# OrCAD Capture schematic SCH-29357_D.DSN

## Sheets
1 TITLE / TOC / REV: title: X-FRDMPT2001EVM; rev: D; company: NXP Semiconductors; note: SCH-29357 PDF: SPF-29357; note: 6501 William Cannon Drive West; note: Austin, TX 78735-8598
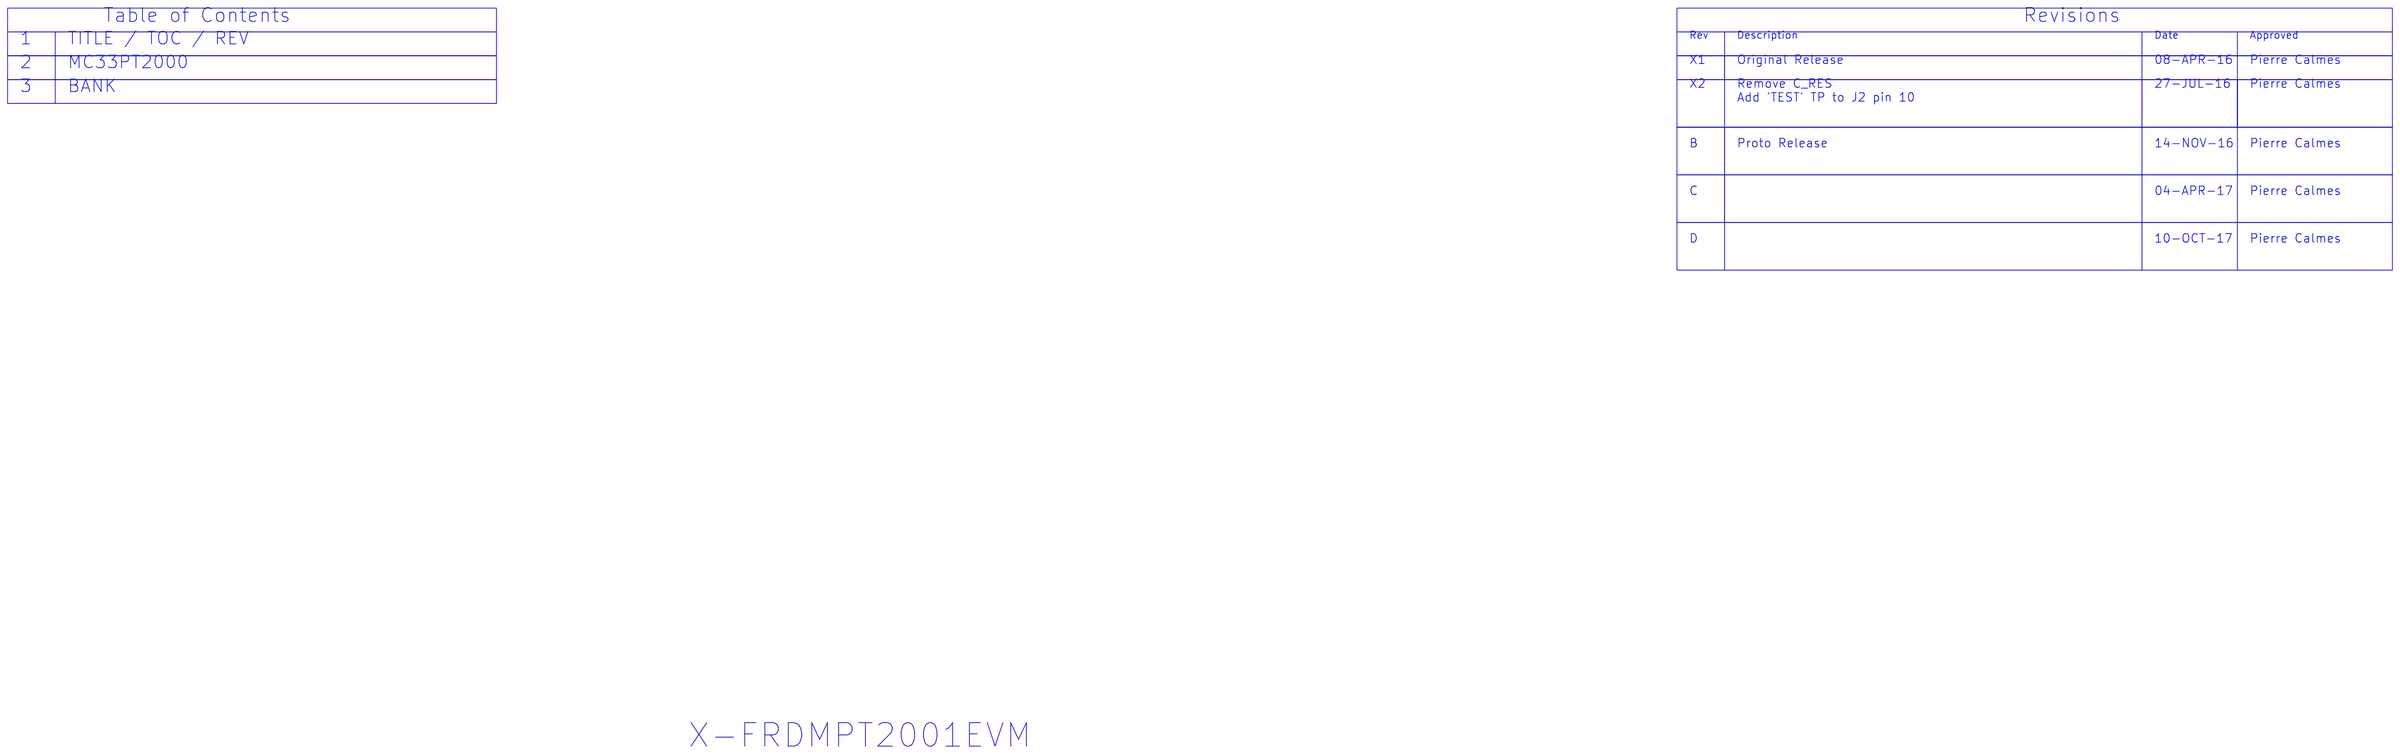
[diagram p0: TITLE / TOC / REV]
2 MC33PT2001: size Custom
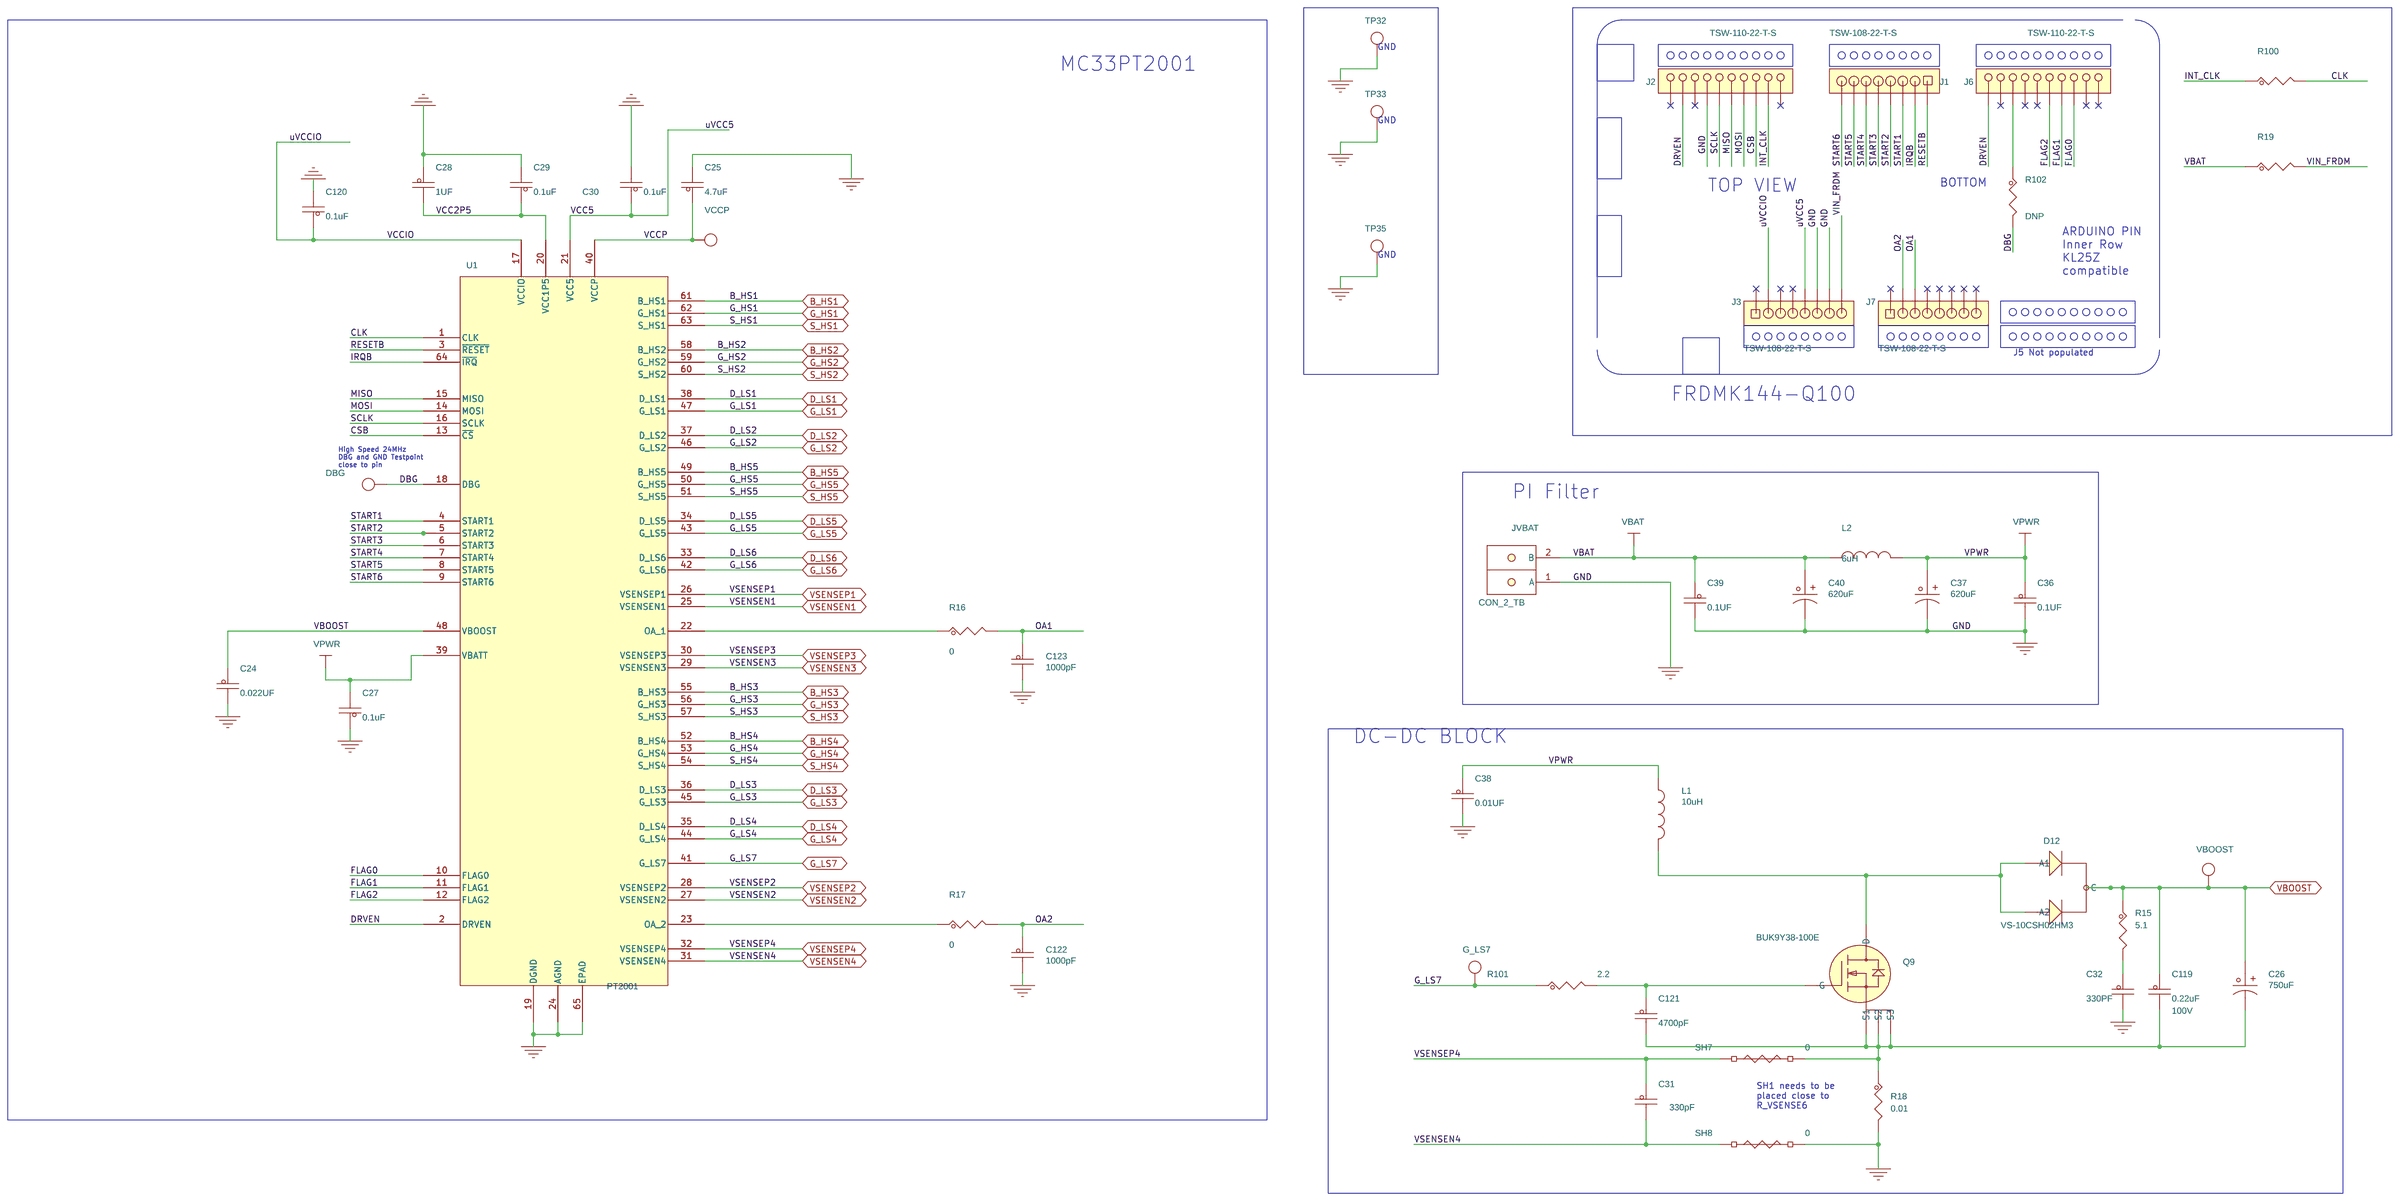
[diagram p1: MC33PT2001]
3 BANK: size Custom
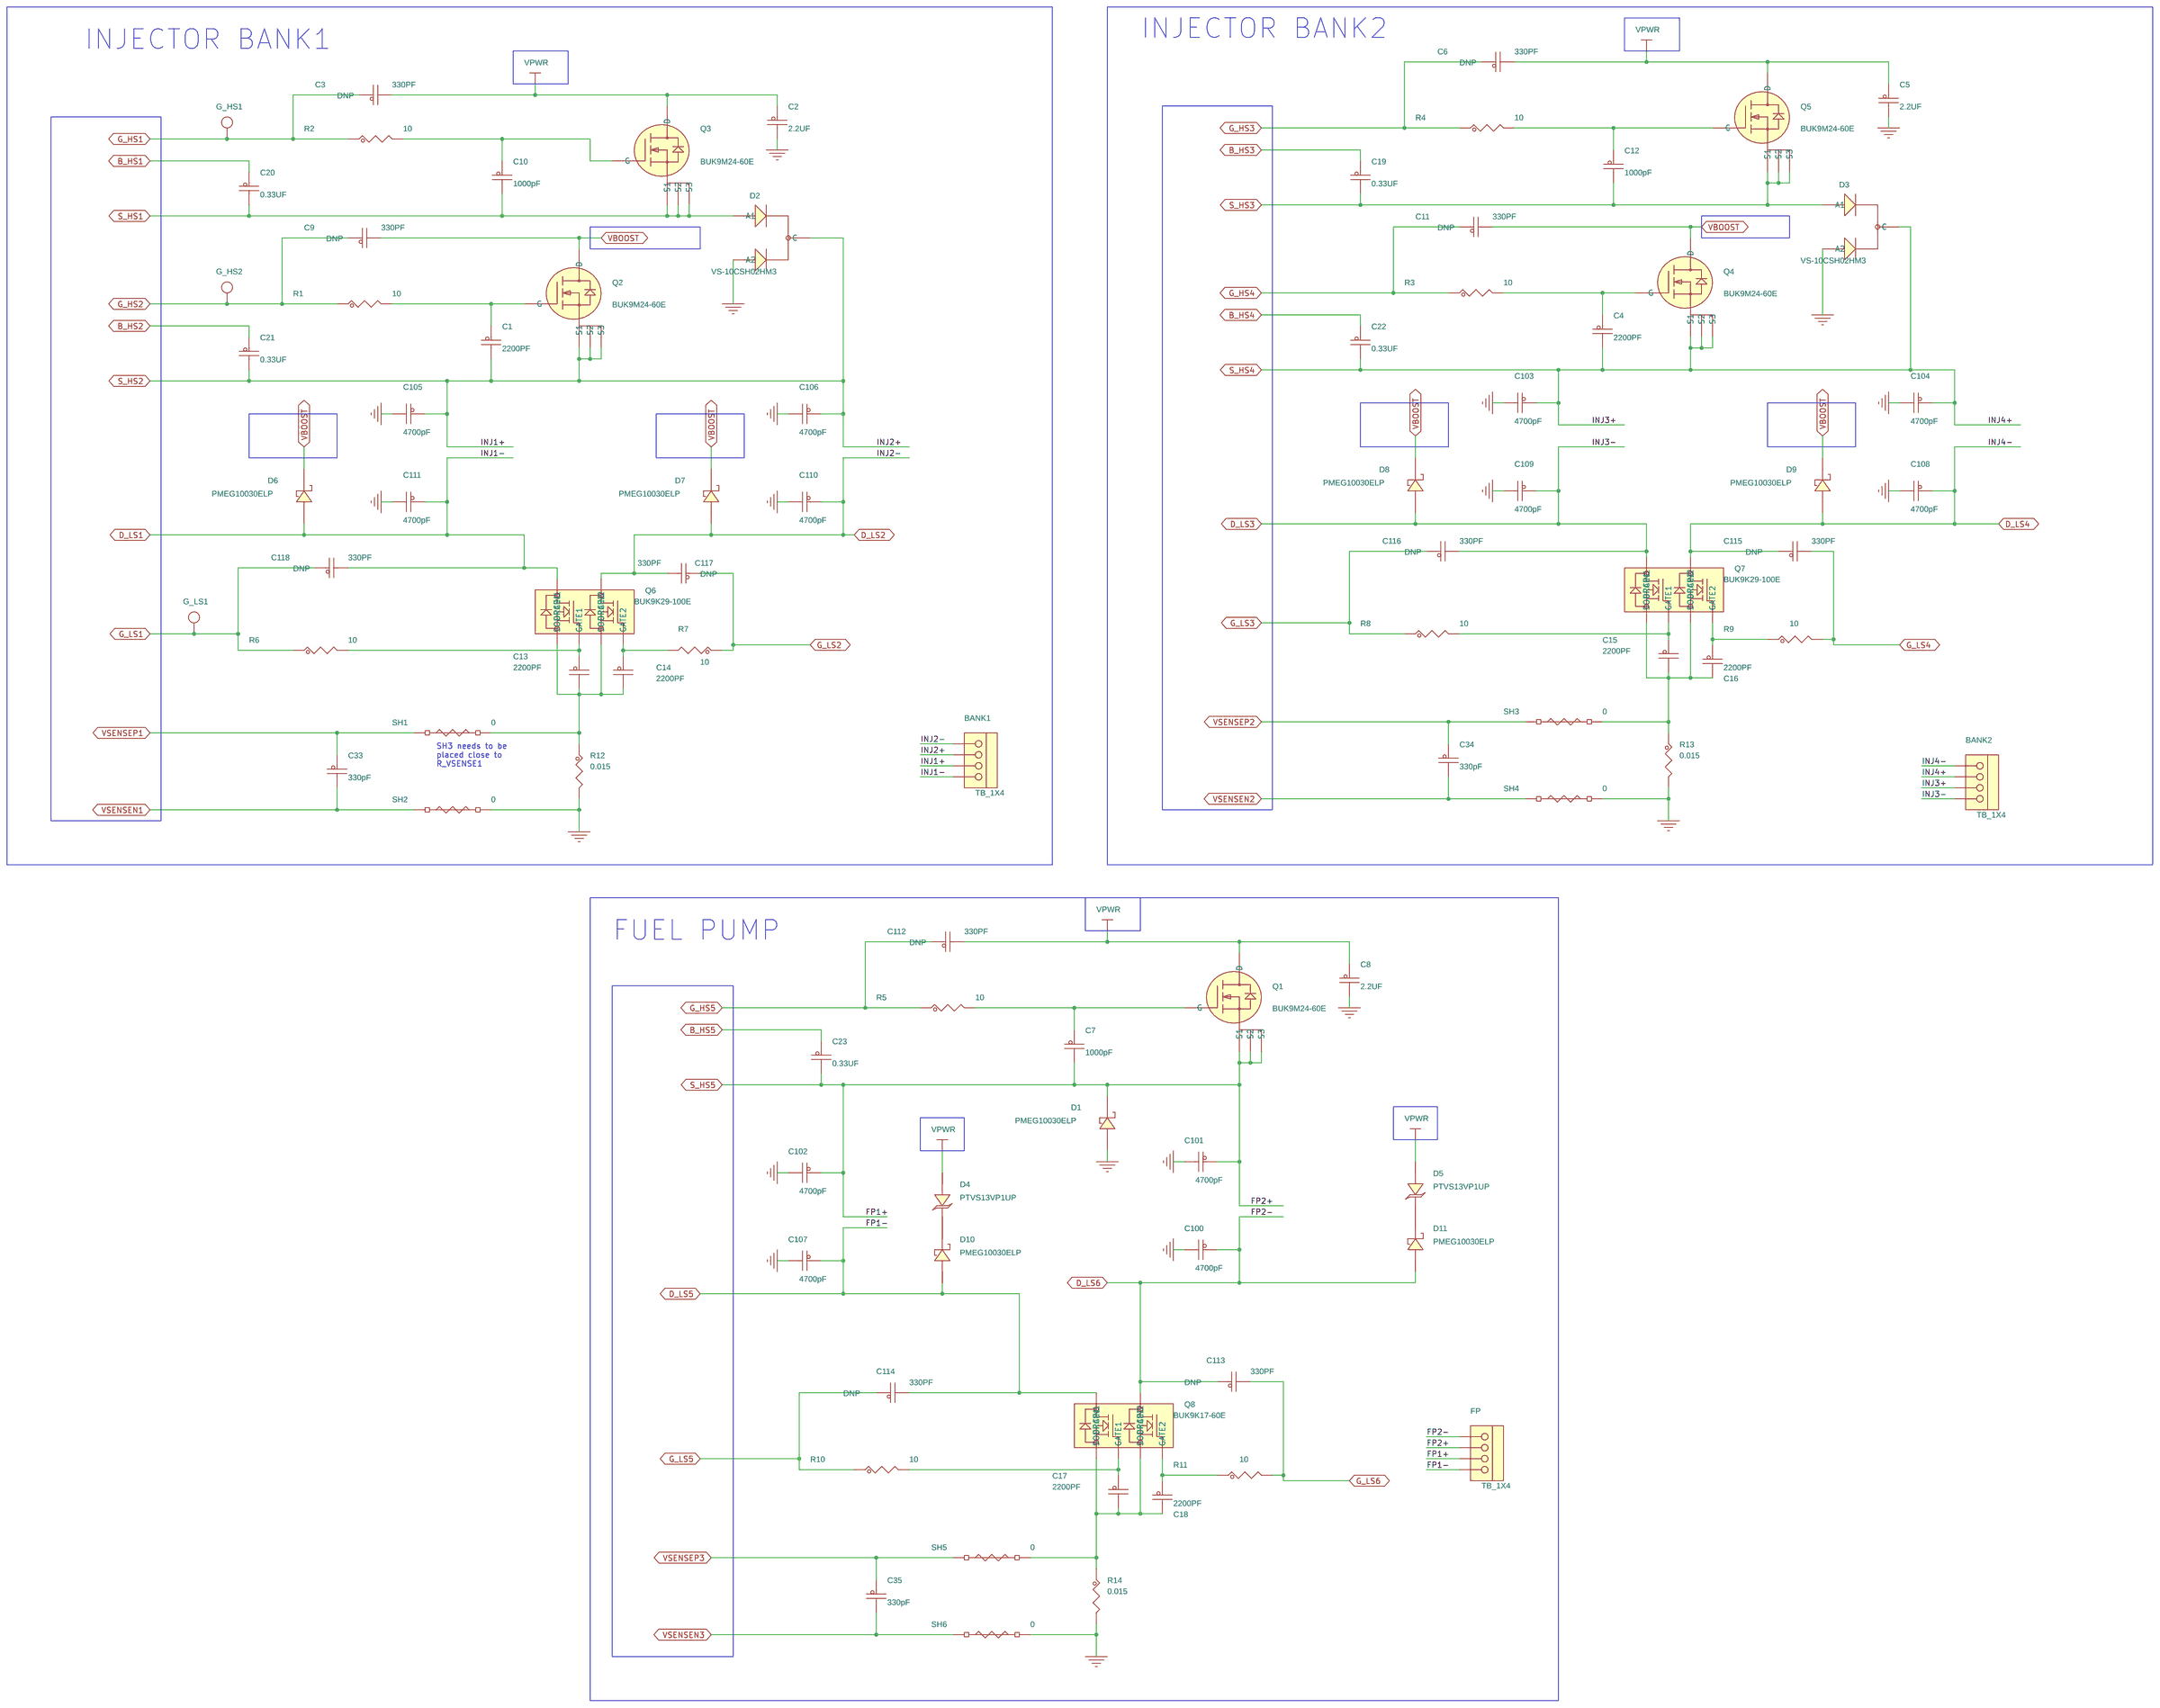
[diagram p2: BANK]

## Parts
sheet BANK
BANK1  TB_1X4  [con4_3p5_14p5x7mm]
BANK2  TB_1X4  [con4_3p5_14p5x7mm]
C1  2200PF  [CC0805_OV]
C2  2.2UF  [CC0805_OV]
C3  330PF  [CC0805_OV]
C4  2200PF  [CC0805_OV]
C5  2.2UF  [CC0805_OV]
C6  330PF  [CC0805_OV]
C7  1000pF  [CC0805_OV]
C8  2.2UF  [CC0805_OV]
C9  330PF  [CC0805_OV]
C10  1000pF  [CC0805_OV]
C11  330PF  [CC0805_OV]
C12  1000pF  [CC0805_OV]
C13  2200PF  [CC0805_OV]
C14  2200PF  [CC0805_OV]
C15  2200PF  [CC0805_OV]
C16  2200PF  [CC0805_OV]
C17  2200PF  [CC0805_OV]
C18  2200PF  [CC0805_OV]
C19  0.33UF  [CC0603_OV]
C20  0.33UF  [CC0603_OV]
C21  0.33UF  [CC0603_OV]
C22  0.33UF  [CC0603_OV]
C23  0.33UF  [CC0603_OV]
C33  330pF  [CC0603_OV]
C34  330pF  [CC0603_OV]
C35  330pF  [CC0603_OV]
C100  4700pF  [CC0805_OV]
C101  4700pF  [CC0805_OV]
C102  4700pF  [CC0805_OV]
C103  4700pF  [CC0805_OV]
C104  4700pF  [CC0805_OV]
C105  4700pF  [CC0805_OV]
C106  4700pF  [CC0805_OV]
C107  4700pF  [CC0805_OV]
C108  4700pF  [CC0805_OV]
C109  4700pF  [CC0805_OV]
C110  4700pF  [CC0805_OV]
C111  4700pF  [CC0805_OV]
C112  330PF  [CC0805_OV]
C113  330PF  [CC0805_OV]
C114  330PF  [CC0805_OV]
C115  330PF  [CC0805_OV]
C116  330PF  [CC0805_OV]
C117  330PF  [CC0805_OV]
C118  330PF  [CC0805_OV]
D1  PMEG10030ELP  [sod-128]
D2  VS-10CSH02HM3  [to_277a]
D3  VS-10CSH02HM3  [to_277a]
D4  PTVS13VP1UP  [sod-128]
D5  PTVS13VP1UP  [sod-128]
D6  PMEG10030ELP  [sod-128]
D7  PMEG10030ELP  [sod-128]
D8  PMEG10030ELP  [sod-128]
D9  PMEG10030ELP  [sod-128]
D10  PMEG10030ELP  [sod-128]
D11  PMEG10030ELP  [sod-128]
FP  TB_1X4  [con4_3p5_14p5x7mm]
G_HS1  TEST POINT ORANGE  [TEST_LOOP]
G_HS2  TEST POINT ORANGE  [TEST_LOOP]
G_LS1  TEST POINT ORANGE  [TEST_LOOP]
Q1  BUK9M24-60E  [LFPAK33_0P65_3P4X2P7]
Q2  BUK9M24-60E  [LFPAK33_0P65_3P4X2P7]
Q3  BUK9M24-60E  [LFPAK33_0P65_3P4X2P7]
Q4  BUK9M24-60E  [LFPAK33_0P65_3P4X2P7]
Q5  BUK9M24-60E  [LFPAK33_0P65_3P4X2P7]
Q6  BUK9K29-100E  [LFPAK56_1P27_4P7X5P3]
Q7  BUK9K29-100E  [LFPAK56_1P27_4P7X5P3]
Q8  BUK9K17-60E  [LFPAK56_1P27_4P7X5P3]
R1  10  [RC0805_OV]
R2  10  [RC0805_OV]
R3  10  [RC0805_OV]
R4  10  [RC0805_OV]
R5  10  [RC0805_OV]
R6  10  [RC0805_OV]
R7  10  [RC0805_OV]
R8  10  [RC0805_OV]
R9  10  [RC0805_OV]
R10  10  [RC0805_OV]
R11  10  [RC0805_OV]
R12  0.015  [rl3264]
R13  0.015  [rl3264]
R14  0.015  [rl3264]
SH1  0  [SH0603]
SH2  0  [SH0603]
SH3  0  [SH0603]
SH4  0  [SH0603]
SH5  0  [SH0603]
SH6  0  [SH0603]
sheet MC33PT2001
C24  0.022UF  [CC0805_OV]
C25  4.7uF  [CC0805_OV]
C26  750uF  [cap_pol_7p5_16p5]
C27  0.1uF  [CC0603_OV]
C28  1UF  [CC0603_OV]
C29  0.1uF  [CC0603_OV]
C30  0.1uF  [CC0603_OV]
C31  330pF  [CC0603_OV]
C32  330PF  [CC0805_OV]
C36  0.1UF  [CC1206_OV]
C37  620uF  [cap_13mm_rad]
C38  0.01UF  [CC0805_OV]
C39  0.1UF  [CC1206_OV]
C40  620uF  [cap_13mm_rad]
C119  0.22uF  [CC0805_OV]
C120  0.1uF  [CC0603_OV]
C121  4700pF  [CC0805_OV]
C122  1000pF  [CC0603_OV]
C123  1000pF  [CC0603_OV]
D12  VS-10CSH02HM3  [to_277a]
DBG  TEST POINT WHITE  [TEST_LOOP]
G_LS7  TEST POINT ORANGE  [TEST_LOOP]
J1  TSW-108-22-T-S  [JUMP1X8-6040]
J2  TSW-110-22-T-S  [hdr110]
J3  TSW-108-22-T-S  [JUMP1X8-6040]
J6  TSW-110-22-T-S  [hdr110]
J7  TSW-108-22-T-S  [JUMP1X8-6040]
JVBAT  CON_2_TB  [con2_tb_5mm]
L1  10uH  [ind_14x12p8]
L2  6uH  [ind2_18mm_th]
Q9  BUK9Y38-100E  [lfpak5_1p27_5x4]
R15  5.1  [RC0603_OV]
R16  0  [RC0603_OV]
R17  0  [RC0603_OV]
R18  0.01  [RC2512]
R19  0  [RC0603_OV]
R100  0  [RC0603_OV]
R101  2.2  [RC0805_OV]
R102  0  [RC0603_OV]
SH7  0  [SH0603]
SH8  0  [SH0603]
TP32  TEST POINT BLACK  [TEST_LOOP]
TP33  TEST POINT BLACK  [TEST_LOOP]
TP35  TEST POINT BLACK  [TEST_LOOP]
U1  PT2001  [LQFP64_EP175MIL]
VBOOST  TEST POINT RED  [TEST_LOOP]
VCCP  TEST POINT RED  [TEST_LOOP]

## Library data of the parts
BANK1 BANK2 FP = CON_HDR_1X4: CON 1X4 TB TH 3.5MM SP 335H -- 138L; AGILE_PN: 210-80422; CAD_APPROVED: Yes; HARD_LOCATION: YES; HEIGHT: 8.5MM; MFG_NAME01: Phoenix Contact; MFG_PN01: 1751264; ROHS: Yes
C1 C4 C13-C18 = CAP_NP: CAP CER 2200PF 25V 20% X7R 0805; AGILE_PN: 150-75211; CAD_APPROVED: YES; FPLIST: CC0805_OV,CC0805,0805_CC; HARD_LOCATION: YES; HEIGHT: 1.4MM; MFG_NAME01: KEMET; MFG_PN01: C0805C222M3RAC; ROHS: Yes; Tolerance: 20%; VOLTAGE: 25V
C2 C5 C8 = CAP_NP: CAP CER 2.2uF 25V 10% X7R 0805; AGILE_PN: 150-75638; CAD_APPROVED: Yes; FPLIST: CC0805_OV,CC0805,0805_CC; HARD_LOCATION: YES; HEIGHT: 1.45MM; MFG_NAME01: AVX; MFG_PN01: 08053C225KAT2A; ROHS: Yes; Tolerance: 10%; VOLTAGE: 25V
C3 C6 C9 C11 C112-C118 = CAP_NP: CAP CER 330PF 100V 5% C0G 0805; AGILE_PN: 150-77353; ASSY_OPT: DNP; CAD_APPROVED: Yes; FPLIST: CC0805_OV,CC0805,0805_CC; HARD_LOCATION: YES; HEIGHT: 0.94MM; MFG_NAME01: AVX; MFG_PN01: 08051A331JAT2A; ROHS: Yes; Tolerance: 5%; VOLTAGE: 100V
C7 C10 C12 = CAP_NP: CAP CER 1000PF 50V 10% X7R 0805; AGILE_PN: 150-75208; CAD_APPROVED: Yes; FPLIST: CC0805_OV,CC0805,0805_CC; HARD_LOCATION: YES; HEIGHT: 0.94MM; MFG_NAME01: AVX; MFG_PN01: 08055C102KAT2A; ROHS: Yes; Tolerance: 10%; VOLTAGE: 50V
C19-C23 = CAP_NP: CAP CER 0.33UF 50V 10% X7R 0603; AGILE_PN: 150-79257; CAD_APPROVED: Yes; FPLIST: CC0603_OV,CC0603,0603_CC; HARD_LOCATION: YES; HEIGHT: 0.9MM; MFG_NAME01: TDK; MFG_PN01: C1608X7R1H334K080AC; ROHS: Yes; Tolerance: 10%; VOLTAGE: 50V
C31 C33-C35 = CAP_NP: CAP CER 330PF 25V 1% C0G 0603; AGILE_PN: 150-77872; CAD_APPROVED: Yes; FPLIST: CC0603_OV,CC0603,0603_CC; HARD_LOCATION: YES; HEIGHT: 0.86MM; MFG_NAME01: AVX; MFG_PN01: 06033A331FAT2A; ROHS: Yes; Tolerance: 1%; VOLTAGE: 25V
C100-C111 C121 = CAP_NP: CAP CER 4700pF 100V 5% C0G 0805; AGILE_PN: 150-78729; CAD_APPROVED: Yes; FPLIST: CC0805_OV,CC0805,0805_CC; HARD_LOCATION: YES; HEIGHT: 0.88MM; MFG_NAME01: KEMET; MFG_PN01: C0805C472J1GACTU; ROHS: Yes; Tolerance: 5%; VOLTAGE: 100V
D1 D6-D11 = DIODE_SCHTKY: DIODE SCH 100V 3A AEC-Q101 SOD128; AGILE_PN: 480-78979; CAD_APPROVED: Yes; HARD_LOCATION: YES; HEIGHT: 1.1MM; MFG_NAME01: NXP SEMICONDUCTORS; ROHS: Yes
D2 D3 D12 = DUALDIODE_CC_SOT23: DIODE RECT 2 x 5A AEC-Q101 TO-277A; AGILE_PN: 480-79720; CAD_APPROVED: Yes; HARD_LOCATION: YES; HEIGHT: 1.2MM; MFG_NAME01: VISHAY INTERTECHNOLOGY; ROHS: Yes; Temp_Range: -65C to +175C
D4 D5 = DIODE_TVS: DIODE TVS UNIDIR 100A 600W 13V AEC-Q101 SOD128; AGILE_PN: 480-79663; CAD_APPROVED: Yes; HARD_LOCATION: YES; HEIGHT: 1.1MM; MFG_NAME01: NXP SEMICONDUCTORS; MFG_PN01: PTVS13VP1UP,115; ROHS: Yes
G_HS1 G_HS2 G_LS1 G_LS7 = TestLoop: TEST POINT ORANGE 40 MIL DRILL 180 MIL TH; AGILE_PN: 210-76025; CAD_APPROVED: Yes; HARD_LOCATION: YES; HEIGHT: 4.8 mm; MFG_NAME01: Keystone Electronics; MFG_PN01: 5003; ROHS: Yes
Q1-Q5 = NMOS_5P: TRAN NMOS PWR  24mOHM 34A 60V LFPAK33; AGILE_PN: 480-79524; CAD_APPROVED: Yes; HARD_LOCATION: YES; HEIGHT: 1 MM; MFG_NAME01: NXP SEMICONDUCTORS; MFG_PN01: BUK9M24-60EX; ROHS: Yes
Q6 Q7 = NMOS_DUAL_8P: TRAN NMOS PWR SW DUAL 29mOHM 30A 100V AEC-Q101 LFPAK56D; AGILE_PN: 480-79204; CAD_APPROVED: Yes; HARD_LOCATION: YES; HEIGHT: 1.15 MM; MFG_NAME01: NXP SEMICONDUCTORS; MFG_PN01: BUK9K29-100E,115; ROHS: Yes
Q8 = NMOS_DUAL_8P: TRAN NMOS PWR SW DUAL 17mOHM 26A 60V AEC-Q101 LFPAK56D; AGILE_PN: 480-79200; CAD_APPROVED: Yes; HARD_LOCATION: YES; HEIGHT: 1.15 MM; MFG_NAME01: NXP SEMICONDUCTORS; MFG_PN01: BUK9K17-60EX; ROHS: Yes
R1-R11 = RES: RES MF 10.0 OHM 1/8W 1% 0805; AGILE_PN: 470-75903; CAD_APPROVED: Yes; FPLIST: RC0805_OV,RC0805,0805_CC; HARD_LOCATION: YES; HEIGHT: 0.70 MM; MFG_NAME01: BOURNS; MFG_PN01: CR0805-FX-10R0ELF; ROHS: Yes; Tolerance: 1%
R12-R14 = RES: RES MF 0.015 OHM 2W 1% 2512; AGILE_PN: 470-80377; CAD_APPROVED: Yes; HARD_LOCATION: YES; HEIGHT: 0.62MM; MFG_NAME01: OHMITE MANUFACTURING; MFG_PN01: MCS3264R015FER; ROHS: Yes; Tolerance: 1%
SH1-SH8 = RES_SHORT-2: ZERO OHM CUT TRACE 0603 PADS; NO PART TO ORDER; AGILE_PN: 470-80018; CAD_APPROVED: Yes; FPLIST: SH0603,SH0603_CC,SH0603-X2_PIN1TO2,SH0603-X2_PIN2TO3; HARD_LOCATION: YES; HEIGHT: 0.1MM; MFG_NAME01: LAYOUT ELEMENT ONLY; MFG_PN01: LAYOUT ELEMENT ONLY; ROHS: Yes
C24 = CAP_NP: CAP CER 0.022UF 50V 10% X7R 0805; AGILE_PN: 150-30206; CAD_APPROVED: Yes; FPLIST: CC0805_OV,CC0805,0805_CC; HARD_LOCATION: YES; HEIGHT: 1.35MM; MFG_NAME01: KEMET; MFG_PN01: C0805C223K5RACTU; ROHS: Yes; Tolerance: 10%; VOLTAGE: 50V
C25 = CAP_NP: CAP CER 4.7uF 50V 20% X5R 0805; AGILE_PN: 150-78922; CAD_APPROVED: Yes; FPLIST: CC0805_OV,CC0805,0805_CC; HARD_LOCATION: YES; HEIGHT: 1.45MM; MFG_NAME01: TDK; MFG_PN01: C2012X5R1H475M; ROHS: Yes; Tolerance: 20%; VOLTAGE: 50V
C26 = CAP_POL: CAP ALEL 750uF 80V 20% TH RADIAL; AGILE_PN: 150-79865; CAD_APPROVED: Yes; HARD_LOCATION: YES; HEIGHT: 31.5MM; MFG_NAME01: UNITED CHEMI-CON INC; MFG_PN01: EGPD800ELL751ML30H; ROHS: Yes; Temp_Range: -40°C - 135°C; Tolerance: 20%; VOLTAGE: 80V
C27 C29 C30 C120 = CAP_NP: CAP CER 0.1uF 50V 10% X7R AEC-Q200 0603; AGILE_PN: 150-79042; CAD_APPROVED: Yes; FPLIST: CC0603_OV,CC0603,0603_CC; HARD_LOCATION: YES; HEIGHT: 0.9 MM; MFG_NAME01: MURATA; MFG_PN01: GCM188R71H104KA57D; ROHS: Yes; Tolerance: 10%; VOLTAGE: 50V
C28 = CAP_NP: CAP CER 1uF 25V 10% X7R AEC-Q200 0603; AGILE_PN: 150-79081; CAD_APPROVED: Yes; FPLIST: CC0603_OV,CC0603,0603_CC; HARD_LOCATION: YES; HEIGHT: 0.9MM; MFG_NAME01: TDK; MFG_PN01: CGA3E1X7R1E105K080AC; ROHS: Yes; Tolerance: 10%; VOLTAGE: 25V
C32 = CAP_NP: CAP CER 330PF 100V 5% C0G 0805; AGILE_PN: 150-77353; CAD_APPROVED: Yes; FPLIST: CC0805_OV,CC0805,0805_CC; HARD_LOCATION: YES; HEIGHT: 0.94MM; MFG_NAME01: AVX; MFG_PN01: 08051A331JAT2A; ROHS: Yes; Tolerance: 5%; VOLTAGE: 100V
C36 C39 = CAP_NP: CAP CER 0.1UF 200V 10% X7R 1206; AGILE_PN: 150-77157; CAD_APPROVED: Yes; FPLIST: CC1206_OV,CC1206,1206_CC; HARD_LOCATION: YES; HEIGHT: 1.8MM; MFG_NAME01: KEMET; MFG_PN01: C1206C104K2RACTU; ROHS: Yes; Tolerance: 10%; VOLTAGE: 200V
C37 C40 = CAP_POL: CAP ALEL 620uF 50V 20% -- TH RADIAL; AGILE_PN: 150-79766; CAD_APPROVED: Yes; HARD_LOCATION: YES; HEIGHT: 21.5MM; MFG_NAME01: UNITED CHEMI-CON INC; MFG_PN01: EGPD500ELL621MK20H; ROHS: Yes; Tolerance: 20%; VOLTAGE: 50V
C38 = CAP_NP: CAP CER 0.01UF 100V 10% X7R 0805; AGILE_PN: 150-30231; CAD_APPROVED: Yes; FPLIST: CC0805_OV,CC0805,0805_CC; HARD_LOCATION: YES; HEIGHT: 1.35MM; MFG_NAME01: MURATA; MFG_PN01: GRM21BR72A103KA01L; ROHS: Yes; Tolerance: 10%; VOLTAGE: 100V
C119 = CAP_NP: CAP CER 0.22UF 100V 20% X7S 0805; AGILE_PN: 150-79088; CAD_APPROVED: Yes; FPLIST: CC0805_OV,CC0805,0805_CC; HARD_LOCATION: YES; HEIGHT: 0.85MM; MFG_NAME01: TDK; MFG_PN01: C2012X7S2A224M/SOFT; ROHS: Yes; Tolerance: 20%; VOLTAGE: 100V
C122 C123 = CAP_NP: CAP CER 1000pF 50V 1% C0G 0603; AGILE_PN: 150-79073; CAD_APPROVED: Yes; FPLIST: CC0603_OV,CC0603,0603_CC; HARD_LOCATION: YES; HEIGHT: 0.9MM; MFG_NAME01: TDK; MFG_PN01: C1608C0G1H102F080AA; ROHS: Yes; Tolerance: 1%; VOLTAGE: 50V
DBG = TestLoop: TEST POINT WHITE 40 MIL DRILL 180 MIL TH 109L; AGILE_PN: 210-75685; CAD_APPROVED: Yes; HARD_LOCATION: YES; HEIGHT: 4.8 MM; MFG_NAME01: KEYSTONE ELECTRONICS; MFG_PN01: 5002; ROHS: Yes
J1 J3 J7 = HDR-1X8: HDR 1X8 TH 100MIL SP 338H SN 300L; AGILE_PN: 210-81229; CAD_APPROVED: Yes; HARD_LOCATION: YES; HEIGHT: 8.59MM; MFG_NAME01: SAMTEC; ROHS: Yes; Temp_Range: 55C to +105C
J2 J6 = CONN_HDR_10X1: HDR 1X10 TH 100MIL SP 338H SN 300L; AGILE_PN: 210-81230; CAD_APPROVED: Yes; HARD_LOCATION: YES; HEIGHT: 8.59MM; MFG_NAME01: SAMTEC; ROHS: Yes; Temp_Range: 55C to +105C
JVBAT = TB2: CON 1X2 TB TH 5MM SP 394H SN; AGILE_PN: 210-77613; CAD_APPROVED: Yes; HARD_LOCATION: YES; HEIGHT: 10MM; MFG_NAME01: CAMDEN ELECTRONICS LTD; MFG_PN01: CTB5000/2; ROHS: Yes
L1 = IND: IND PWR 10uH@100KHZ 16A 20% AEC-Q200 SMT; AGILE_PN: 180-78393; CAD_APPROVED: Yes; HARD_LOCATION: YES; HEIGHT: 5MM; MFG_NAME01: Bourns; MFG_PN01: SRP1245A-100M; PART_TYPE: INDUCTOR\POWER; ROHS: Yes; TOL: 20%; Tolerance: 20%
L2 = INDUCTOR: IND ROD CHK 6uH@10KHZ 10A 25% TH; AGILE_PN: 180-78068; CAD_APPROVED: Yes; HARD_LOCATION: YES; HEIGHT: 8.6MM; MFG_NAME01: WURTH ELEKTRONIK EISOS GMBH & CO. KG; MFG_PN01: 744710610; PART_TYPE: INDUCTOR\POWER; ROHS: Yes
Q9 = NMOS_5P: TRAN NMOS PWR 30A 100V AEC-Q101 LFPAK56; AGILE_PN: 480-78977; CAD_APPROVED: Yes; HARD_LOCATION: YES; HEIGHT: 1.2MM; MFG_NAME01: NXP SEMICONDUCTORS; MFG_PN01: BUK9Y38-100E,115; ROHS: Yes
R15 = RES: RES MF 5.1 OHM 1/10W 5% 0603; AGILE_PN: 470-30450; CAD_APPROVED: Yes; FPLIST: RC0603_OV,RC0603,0603_CC; HARD_LOCATION: YES; HEIGHT: 0.55 MM; MFG_NAME01: KOA SPEER; MFG_PN01: RK73B1JTTD5R1J; ROHS: Yes; Tolerance: 5%
R16 R17 = RES: RES MF ZERO OHM 1/10W -- 0603; AGILE_PN: 470-80866; CAD_APPROVED: Yes; FPLIST: RC0603_OV,RC0603,R603-X2,0603_CC; HARD_LOCATION: YES; HEIGHT: 0.6MM; MFG_NAME01: BOURNS; MFG_PN01: CR0603J/000ELF; ROHS: Yes
R18 = RES: RES MF 0.01 OHM 1.0W 1% 2512; AGILE_PN: 470-75760; CAD_APPROVED: Yes; HARD_LOCATION: YES; HEIGHT: 1.016 MM; MFG_NAME01: VISHAY INTERTECHNOLOGY; MFG_PN01: WSL2512R0100FEA; ROHS: Yes; Tolerance: 1%
R19 R100 = RES: RES MF ZERO OHM 1/10W -- AEC-Q200 0603; AGILE_PN: 470-75407; CAD_APPROVED: Yes; FPLIST: RC0603_OV,RC0603,R603-X2,0603_CC; HARD_LOCATION: YES; HEIGHT: 0.6MM; MFG_NAME01: KOA SPEER; MFG_PN01: RK73Z1JTTD; ROHS: Yes; Tolerance: 1%
R101 = RES: RES MF 2.20 OHM 1/8W 1% 0805; AGILE_PN: 470-76034; CAD_APPROVED: Yes; FPLIST: RC0805_OV,RC0805,0805_CC; HARD_LOCATION: YES; MFG_NAME01: BOURNS; MFG_PN01: CRL0805-FW-2R20ELF; ROHS: Yes; Tolerance: 1%
R102 = RES: RES MF ZERO OHM 1/10W -- AEC-Q200 0603; AGILE_PN: 470-75407; ASSY_OPT: DNP; CAD_APPROVED: Yes; FPLIST: RC0603_OV,RC0603,R603-X2,0603_CC; HARD_LOCATION: YES; HEIGHT: 0.6MM; MFG_NAME01: KOA SPEER; MFG_PN01: RK73Z1JTTD; ROHS: Yes; Tolerance: 1%
TP32 TP33 TP35 = TestLoop: TEST POINT BLACK 40 MIL DRILL 180 MIL TH 109L; AGILE_PN: 210-75683; CAD_APPROVED: Yes; HARD_LOCATION: YES; HEIGHT: 4.8mm; MFG_NAME01: KEYSTONE ELECTRONICS; MFG_PN01: 5001; ROHS: Yes
U1 = PT2001_LQFP64_EP: IC CTLER AUTOMOTIVE ENGINE/SMART GATE 5.5-72V LQFP64; AGILE_PN: TMP-WF-31561; CAD_APPROVED: Yes; HARD_LOCATION: YES; HEIGHT: 1.6MM; MFG_NAME01: NXP SEMICONDUCTORS; PRE_APN: 312-81863; ROHS: Yes
VBOOST VCCP = TestLoop: TEST POINT RED 40 MIL DRILL 180 MIL TH 109L; AGILE_PN: 210-75684; CAD_APPROVED: Yes; HARD_LOCATION: YES; HEIGHT: 4.8 MM; MFG_NAME01: KEYSTONE ELECTRONICS; MFG_PN01: 5000; ROHS: Yes

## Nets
GND: C2.2 C5.2 C8.2 C24.2 C25.2 C27.1 C28.1 C29.2 C30.2 C32.2 C36.2 C37.2 C38.2 C39.2 C40.2 C100.2 C101.2 C102.2 C103.2 C104.2 C105.2 C106.2 C107.2 C108.2 C109.2 C110.2 C111.2 C120.2 C122.2 C123.2 D1.A D2.2(A2) D3.2(A2) J2.7 J3.6 J3.7 JVBAT.1(A) R12.2 R13.2 R14.2 R18.2 SH2.2 SH4.2 SH6.2 SH8.2 TP32.1(Pin1) TP33.1(Pin1) TP35.1(Pin1) U1.19(DGND) U1.24(AGND) U1.65(EPAD)
VBAT: C39.1 C40.1 JVBAT.2(B) L2.1 R19.1
VCC2P5: C28.2 C29.1 U1.20(VCC1P5)
VCC5: C30.1 J3.5 U1.21(VCC5)
VCCIO: C120.1 J3.2 U1.17(VCCIO)
VCCP: C25.1 U1.40(VCCP) VCCP.1(Pin1)
VIN_FRDM: J3.8 R19.2
B_HS1: C20.1 U1.61(B_HS1)
B_HS2: C21.1 U1.58(B_HS2)
B_HS3: C19.1 U1.55(B_HS3)
B_HS4: C22.1 U1.52(B_HS4)
B_HS5: C23.1 U1.49(B_HS5)
CLK: R100.2 U1.1(CLK)
CSB: J2.3 U1.13(~{CS})
D_LS1: BANK1.4 C111.1 C118.2 D6.A Q6.6(DRAIN1) U1.38(D_LS1)
D_LS2: BANK1.1 C110.1 C117.2 D7.A Q6.5(DRAIN2) U1.37(D_LS2)
D_LS3: BANK2.4 C109.1 C116.2 D8.A Q7.6(DRAIN1) U1.36(D_LS3)
D_LS4: BANK2.1 C108.1 C115.1 D9.A Q7.5(DRAIN2) U1.35(D_LS4)
D_LS5: C107.1 C114.2 D10.A FP.4 Q8.6(DRAIN1) U1.34(D_LS5)
D_LS6: C100.1 C113.1 D11.A FP.1 Q8.5(DRAIN2) U1.33(D_LS6)
DBG: DBG.1(Pin1) R102.2 U1.18(DBG)
DRVEN: J2.9 J6.10 U1.2(DRVEN)
FLAG0: J6.3 U1.10(FLAG0)
FLAG1: J6.4 U1.11(FLAG1)
FLAG2: J6.5 U1.12(FLAG2)
G_HS1: C3.1 G_HS1.1(Pin1) R2.1 U1.62(G_HS1)
G_HS2: C9.1 G_HS2.1(Pin1) R1.1 U1.59(G_HS2)
G_HS3: C6.1 R4.1 U1.56(G_HS3)
G_HS4: C11.1 R3.1 U1.53(G_HS4)
G_HS5: C112.1 R5.1 U1.50(G_HS5)
G_LS1: C118.1 G_LS1.1(Pin1) R6.1 U1.47(G_LS1)
G_LS2: C117.1 R7.1 U1.46(G_LS2)
G_LS3: C116.1 R8.1 U1.45(G_LS3)
G_LS4: C115.2 R9.2 U1.44(G_LS4)
G_LS5: C114.1 R10.1 U1.43(G_LS5)
G_LS6: C113.2 R11.2 U1.42(G_LS6)
G_LS7: G_LS7.1(Pin1) R101.1 U1.41(G_LS7)
INT_CLK: J2.2 R100.1
IRQB: J1.2 U1.64(~{IRQ})
MISO: J2.5 U1.15(MISO)
MOSI: J2.4 U1.14(MOSI)
OA1: C123.1 J7.3 R16.2
OA2: C122.1 J7.2 R17.2
RESETB: J1.1 U1.3(~{RESET})
S_HS1: C10.2 C20.2 D2.1(A1) Q3.1(S1) Q3.2(S2) Q3.3(S3) U1.63(S_HS1)
S_HS2: BANK1.2 BANK1.3 C1.2 C21.2 C105.1 C106.1 D2.3(C) Q2.1(S1) Q2.2(S2) Q2.3(S3) U1.60(S_HS2)
S_HS3: C12.2 C19.2 D3.1(A1) Q5.1(S1) Q5.2(S2) Q5.3(S3) U1.57(S_HS3)
S_HS4: BANK2.2 BANK2.3 C4.2 C22.2 C103.1 C104.1 D3.3(C) Q4.1(S1) Q4.2(S2) Q4.3(S3) U1.54(S_HS4)
S_HS5: C7.2 C23.2 C101.1 C102.1 D1.C FP.2 FP.3 Q1.1(S1) Q1.2(S2) Q1.3(S3) U1.51(S_HS5)
SCLK: J2.6 U1.16(SCLK)
START1: J1.3 U1.4(START1)
START2: J1.4 U1.5(START2)
START3: J1.5 U1.6(START3)
START4: J1.6 U1.7(START4)
START5: J1.7 U1.8(START5)
START6: J1.8 U1.9(START6)
VBOOST: C9.2 C11.2 C24.1 C26.1 C119.1 D6.C D7.C D8.C D9.C D12.3(C) Q2.5(D) Q4.5(D) R15.1 U1.48(VBOOST) VBOOST.1(Pin1)
VPWR: C2.1 C3.2 C5.1 C6.2 C8.1 C27.2 C36.1 C37.1 C38.1 C112.2 D4.A D5.A L1.1 L2.2 Q1.5(D) Q3.5(D) Q5.5(D) U1.39(VBATT)
VSENSEN1: C33.2 SH2.1 U1.25(VSENSEN1)
VSENSEN2: C34.2 SH4.1 U1.27(VSENSEN2)
VSENSEN3: C35.2 SH6.1 U1.29(VSENSEN3)
VSENSEN4: C31.2 SH8.1 U1.31(VSENSEN4)
VSENSEP1: C33.1 SH1.1 U1.26(VSENSEP1)
VSENSEP2: C34.1 SH3.1 U1.28(VSENSEP2)
VSENSEP3: C35.1 SH5.1 U1.30(VSENSEP3)
VSENSEP4: C31.1 SH7.1 U1.32(VSENSEP4)
N20093426: C13.2 C14.2 Q6.1(SOURCE1) Q6.3(SOURCE2) R12.1 SH1.2
N20107863: D12.1(A1) D12.2(A2) L1.2 Q9.5(D)
N20116408: C15.2 C16.2 Q7.1(SOURCE1) Q7.3(SOURCE2) R13.1 SH3.2
N20116444: C12.1 Q5.4(G) R4.2
N20116468: C4.1 Q4.4(G) R3.2
N20122153: C26.2 C119.2 C121.2 Q9.1(S1) Q9.2(S2) Q9.3(S3) R18.1 SH7.2
N20147861: C17.2 C18.2 Q8.1(SOURCE1) Q8.3(SOURCE2) R14.1 SH5.2
N20148840: C7.1 Q1.4(G) R5.2
N20162014: R16.1 U1.22(OA_1)
N20162068: R17.1 U1.23(OA_2)
N20222938: C32.1 R15.2
N20239183: C10.1 Q3.4(G) R2.2
N20239217: C1.1 Q2.4(G) R1.2
N20239233: C13.1 Q6.2(GATE1) R6.2
N20272245: C121.1 Q9.4(G) R101.2
N20316343: J6.8 R102.1
N20388560: C14.1 Q6.4(GATE2) R7.2
N20389779: C16.1 Q7.4(GATE2) R9.1
N20393710: C15.1 Q7.2(GATE1) R8.2
N20487459: C18.1 Q8.4(GATE2) R11.1
N20487503: C17.1 Q8.2(GATE1) R10.2
N20557727: D4.C D10.C
N20557728: D5.C D11.C

Not connected (* = marked no-connect by the designer): J2 1* 8* 10*; J3 1* 3* 4*; J6 1* 2* 6* 7* 9*; J7 1* 4* 5* 6* 7* 8*

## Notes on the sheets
sheet 1
- Table of Contents
- Revisions
- 1
- TITLE / TOC / REV
- Rev
- Description
- Date
- Approved
- 2
- MC33PT2000
- X1
- Original Release
- 08-APR-16
- Pierre Calmes
- 3
- BANK
- X2
- Remove C_RES
  Add 'TEST' TP to J2 pin 10
- 27-JUL-16
- Pierre Calmes
- B
- Proto Release
- 14-NOV-16
- Pierre Calmes
- C
- 04-APR-17
- Pierre Calmes
- D
- 10-OCT-17
- Pierre Calmes
- X-FRDMPT2001EVM
sheet 2
- MC33PT2001
- GND
- GND
- TOP VIEW
- BOTTOM
- ARDUINO PIN
  Inner Row
  KL25Z
  compatible
- GND
- J5 Not populated
- FRDMK144-Q100
- High Speed 24MHz
  DBG and GND Testpoint
  close to pin
- PI Filter
- DC-DC BLOCK
- SH1 needs to be
  placed close to
  R_VSENSE6
sheet 3
- INJECTOR BANK2
- INJECTOR BANK1
- SH3 needs to be
  placed close to
  R_VSENSE1
- FUEL PUMP
